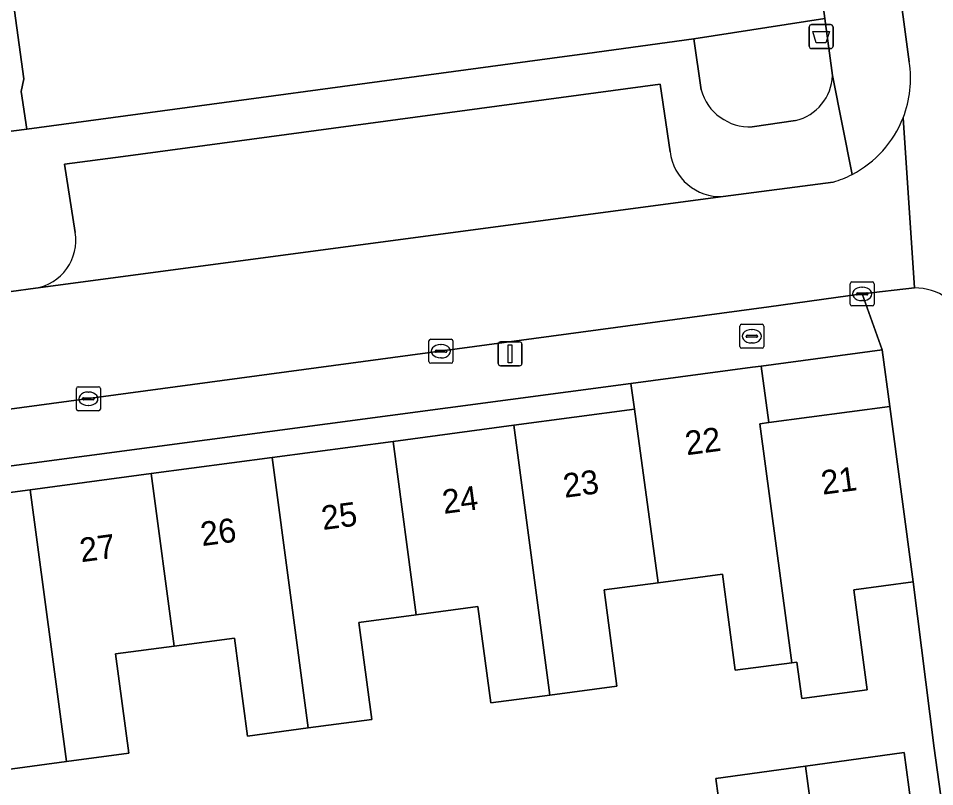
# Model space of a CAD drawing. Extents: x 163147 to 163550, y 380933 to 381639.
# Drawn here: x 163393.71 to 163431.91, y 381151.62 to 381183.65 of the extents above; entities that cross this region are included whole.
import ezdxf

# ---------------------------------------------------------------- set-up
doc = ezdxf.new("R2010")
doc.units = 0
for name, color, linetype in [('IMGEO_Afvalbak', 7, 'Continuous'), ('IMGEO_Brandkraan', 7, 'Continuous'), ('IMGEO_Erf', 7, 'Continuous'), ('IMGEO_Groenvoorziening', 7, 'Continuous'), ('IMGEO_Kolk', 7, 'Continuous'), ('IMGEO_Lichtmast', 7, 'Continuous'), ('IMGEO_Muur', 7, 'Continuous'), ('IMGEO_Pand', 7, 'Continuous'), ('IMGEO_Pand_nummerreeks', 7, 'Continuous'), ('IMGEO_Parkeervlak_open', 7, 'Continuous'), ('IMGEO_Rijbaan_lokaal_open', 7, 'Continuous'), ('IMGEO_Voetpad_gesloten', 7, 'Continuous'), ('IMGEO_Voetpad_open', 7, 'Continuous')]:
    doc.layers.add(name, color=color, linetype=linetype)

msp = doc.modelspace()

# ---------------------------------------------------------------- linework, layer by layer
at = {"layer": 'IMGEO_Afvalbak'}
for p, q in [((163426.682, 381182.493), (163426.682, 381183.293)), ((163426.682, 381183.293), (163426.682, 381182.493)), ((163426.782, 381183.393), (163427.572, 381183.393)), ((163427.572, 381183.393), (163426.782, 381183.393)), ((163427.672, 381183.293), (163427.672, 381182.493)), ((163427.672, 381182.493), (163427.672, 381183.293)), ((163427.572, 381182.393), (163426.782, 381182.393)), ((163426.782, 381182.393), (163427.572, 381182.393))]:
    msp.add_line(p, q, dxfattribs=at)
msp.add_lwpolyline([(163426.825, 381183.107), (163427.529, 381183.107), (163427.38, 381182.637), (163426.974, 381182.637), (163426.825, 381183.107)], dxfattribs=at)
for centre, start, end in [((163426.782, 381183.293), 90, 180), ((163426.782, 381183.293), 90, 180), ((163427.572, 381183.293), 0, 90), ((163427.572, 381183.293), 360, 90), ((163426.782, 381182.493), 180, 270), ((163426.782, 381182.493), 180, 270), ((163427.572, 381182.493), 270, 0), ((163427.572, 381182.493), 270, 0)]:
    msp.add_arc(centre, 0.1, start, end, dxfattribs=at)
at = {"layer": 'IMGEO_Brandkraan'}
for p, q in [((163423.863, 381170.899), (163424.715, 381170.899)), ((163423.788, 381169.973), (163423.788, 381170.825)), ((163424.276, 381170.679), (163424.301, 381170.679)), ((163424.789, 381170.825), (163424.789, 381169.973)), ((163424.047, 381170.393), (163424.047, 381170.405)), ((163424.485, 381170.356), (163424.087, 381170.356)), ((163424.09, 381170.442), (163424.488, 381170.442)), ((163424.299, 381170.119), (163424.274, 381170.119)), ((163424.531, 381170.405), (163424.531, 381170.393)), ((163424.715, 381169.899), (163423.863, 381169.899))]:
    msp.add_line(p, q, dxfattribs=at)
for points in [[(163423.863, 381170.899), (163424.715, 381170.899)], [(163423.788, 381169.973), (163423.788, 381170.825)], [(163424.789, 381170.825), (163424.789, 381169.973)], [(163424.715, 381169.899), (163423.863, 381169.899)]]:
    msp.add_lwpolyline(points, dxfattribs=at)
for centre, radius, start, end in [((163423.865, 381170.823), 0.0765, 91.552, 178.448), ((163423.865, 381170.823), 0.0765, 91.552, 178.448), ((163424.713, 381170.823), 0.0765, 1.552, 88.448), ((163424.713, 381170.823), 0.0765, 1.552, 88.448), ((163424.087, 381170.402), 0.0403, 85.8775, 175.7526), ((163424.084, 381170.392), 0.0366, 178.938, 274.7102), ((163424.488, 381170.399), 0.043, 264.8664, 352.4533), ((163424.492, 381170.404), 0.0386, 1.7309, 96.639), ((163423.865, 381169.975), 0.0765, 181.552, 268.448), ((163423.865, 381169.975), 0.0765, 181.552, 268.448), ((163424.713, 381169.975), 0.0765, 271.552, 358.448), ((163424.713, 381169.975), 0.0765, 271.552, 358.448)]:
    msp.add_arc(centre, radius, start, end, dxfattribs=at)
for centre, major_axis, ratio, start_param, end_param in [((163424.275, 381170.399), (-0.387, 0.002), 0.722429, 4.712389, 7.853982), ((163424.3, 381170.399), (-0.39, 0.002), 0.717154, 1.570796, 4.712389)]:
    msp.add_ellipse(centre, major_axis=major_axis, ratio=ratio, start_param=start_param, end_param=end_param, dxfattribs=at)
at = {"layer": 'IMGEO_Erf'}
for points in [[(163424.677, 381169.157), (163424.991, 381166.799), (163430.04, 381167.473), (163429.716, 381169.834)], [(163368.864, 381161.727), (163369.01, 381160.644), (163374.049, 381161.316), (163379.091, 381161.987), (163384.131, 381162.659), (163389.171, 381163.33), (163394.211, 381164.002), (163399.252, 381164.673), (163404.292, 381165.345), (163409.333, 381166.017), (163414.374, 381166.688), (163419.394, 381167.357), (163419.25, 381168.435)]]:
    msp.add_lwpolyline(points, close=True, dxfattribs=at)
for points in [[(163432.293, 381150.328), (163431.895, 381153.22), (163431.015, 381160.154), (163428.536, 381159.824), (163429.09, 381155.665), (163426.367, 381155.302), (163426.165, 381156.816), (163425.955, 381156.788), (163423.599, 381156.475), (163423.065, 381160.483), (163420.38, 381160.125), (163418.128, 381159.825), (163418.662, 381155.814), (163415.874, 381155.442), (163413.405, 381155.113), (163412.871, 381159.126), (163410.298, 381158.783), (163407.907, 381158.464), (163408.445, 381154.424), (163405.797, 381154.071), (163403.262, 381153.733), (163402.718, 381157.814), (163400.212, 381157.48), (163397.769, 381157.155), (163398.32, 381153.012), (163395.724, 381152.666), (163393.158, 381152.324)], [(163423.179, 381149.073), (163422.784, 381151.966), (163426.53, 381152.481), (163430.634, 381153.046), (163431.032, 381150.154)]]:
    msp.add_lwpolyline(points, dxfattribs=at)
at = {"layer": 'IMGEO_Groenvoorziening'}
for points in [[(163392.619, 381190.656), (163393.942, 381181.127), (163393.833, 381180.6), (163394.068, 381179.029), (163416.481, 381182.062), (163417.426, 381182.19), (163421.871, 381182.792), (163427.334, 381183.638), (163426.58, 381189.302), (163426.448, 381190.297)], [(163427.649, 381181.274), (163427.334, 381183.638), (163421.871, 381182.792), (163422.171, 381180.674)], [(163424.308, 381179.127), (163426.103, 381179.391)]]:
    msp.add_lwpolyline(points, dxfattribs=at)
for centre, radius, start, end in [((163425.656, 381181.334), 1.994, 282.9625, 358.2634), ((163424.207, 381181.237), 2.112, 195.4506, 272.7469)]:
    msp.add_arc(centre, radius, start, end, dxfattribs=at)
at = {"layer": 'IMGEO_Kolk'}
for p, q in [((163428.386, 381171.736), (163428.386, 381172.588)), ((163428.461, 381172.662), (163429.313, 381172.662)), ((163428.874, 381172.442), (163428.899, 381172.442)), ((163429.387, 381172.588), (163429.387, 381171.736)), ((163428.645, 381172.156), (163428.645, 381172.168)), ((163429.083, 381172.119), (163428.685, 381172.119)), ((163428.688, 381172.205), (163429.086, 381172.205)), ((163429.129, 381172.168), (163429.129, 381172.156)), ((163429.313, 381171.662), (163428.461, 381171.662)), ((163428.897, 381171.882), (163428.872, 381171.882)), ((163410.828, 381169.349), (163410.828, 381170.201)), ((163410.903, 381170.275), (163411.755, 381170.275)), ((163411.829, 381170.201), (163411.829, 381169.349)), ((163411.087, 381169.769), (163411.087, 381169.781)), ((163411.525, 381169.732), (163411.127, 381169.732)), ((163411.13, 381169.818), (163411.528, 381169.818)), ((163411.316, 381170.055), (163411.341, 381170.055)), ((163411.571, 381169.781), (163411.571, 381169.769)), ((163411.339, 381169.495), (163411.314, 381169.495)), ((163411.755, 381169.275), (163410.903, 381169.275)), ((163396.131, 381167.365), (163396.131, 381168.217)), ((163396.206, 381168.291), (163397.058, 381168.291)), ((163397.132, 381168.217), (163397.132, 381167.365)), ((163396.39, 381167.785), (163396.39, 381167.797)), ((163396.433, 381167.834), (163396.831, 381167.834)), ((163396.619, 381168.071), (163396.644, 381168.071)), ((163396.874, 381167.797), (163396.874, 381167.785)), ((163396.828, 381167.748), (163396.43, 381167.748)), ((163396.642, 381167.511), (163396.617, 381167.511)), ((163397.058, 381167.291), (163396.206, 381167.291))]:
    msp.add_line(p, q, dxfattribs=at)
for points in [[(163428.386, 381171.736), (163428.386, 381172.588)], [(163428.461, 381172.662), (163429.313, 381172.662)], [(163429.387, 381172.588), (163429.387, 381171.736)], [(163429.313, 381171.662), (163428.461, 381171.662)], [(163410.828, 381169.349), (163410.828, 381170.201)], [(163410.903, 381170.275), (163411.755, 381170.275)], [(163411.829, 381170.201), (163411.829, 381169.349)], [(163411.755, 381169.275), (163410.903, 381169.275)], [(163396.131, 381167.365), (163396.131, 381168.217)], [(163396.206, 381168.291), (163397.058, 381168.291)], [(163397.132, 381168.217), (163397.132, 381167.365)], [(163397.058, 381167.291), (163396.206, 381167.291)]]:
    msp.add_lwpolyline(points, dxfattribs=at)
for centre, radius, start, end in [((163428.463, 381172.586), 0.0765, 91.552, 178.448), ((163428.463, 381172.586), 0.0765, 91.552, 178.448), ((163429.311, 381172.586), 0.0765, 1.552, 88.448), ((163429.311, 381172.586), 0.0765, 1.552, 88.448), ((163428.685, 381172.165), 0.0403, 85.8775, 175.7526), ((163428.682, 381172.155), 0.0366, 178.938, 274.7102), ((163429.086, 381172.162), 0.043, 264.8664, 352.4533), ((163429.09, 381172.167), 0.0386, 1.7309, 96.639), ((163428.463, 381171.738), 0.0765, 181.552, 268.448), ((163428.463, 381171.738), 0.0765, 181.552, 268.448), ((163429.311, 381171.738), 0.0765, 271.552, 358.448), ((163429.311, 381171.738), 0.0765, 271.552, 358.448), ((163410.905, 381170.199), 0.0765, 91.552, 178.448), ((163410.905, 381170.199), 0.0765, 91.552, 178.448), ((163411.753, 381170.199), 0.0765, 1.552, 88.448), ((163411.753, 381170.199), 0.0765, 1.552, 88.448), ((163411.127, 381169.778), 0.0403, 85.8775, 175.7526), ((163411.124, 381169.768), 0.0366, 178.938, 274.7102), ((163411.528, 381169.775), 0.043, 264.8664, 352.4533), ((163411.532, 381169.78), 0.0386, 1.7309, 96.639), ((163410.905, 381169.351), 0.0765, 181.552, 268.448), ((163410.905, 381169.351), 0.0765, 181.552, 268.448), ((163411.753, 381169.351), 0.0765, 271.552, 358.448), ((163411.753, 381169.351), 0.0765, 271.552, 358.448), ((163396.208, 381168.215), 0.0765, 91.552, 178.448), ((163396.208, 381168.215), 0.0765, 91.552, 178.448), ((163397.056, 381168.215), 0.0765, 1.552, 88.448), ((163397.056, 381168.215), 0.0765, 1.552, 88.448), ((163396.43, 381167.794), 0.0403, 85.8775, 175.7526), ((163396.835, 381167.796), 0.0386, 1.7309, 96.639), ((163396.427, 381167.784), 0.0366, 178.938, 274.7102), ((163396.831, 381167.791), 0.043, 264.8664, 352.4533), ((163396.208, 381167.367), 0.0765, 181.552, 268.448), ((163396.208, 381167.367), 0.0765, 181.552, 268.448), ((163397.056, 381167.367), 0.0765, 271.552, 358.448), ((163397.056, 381167.367), 0.0765, 271.552, 358.448)]:
    msp.add_arc(centre, radius, start, end, dxfattribs=at)
for centre, major_axis, ratio, start_param, end_param in [((163428.873, 381172.162), (-0.387, 0.002), 0.722429, 4.712389, 7.853982), ((163428.898, 381172.162), (-0.39, 0.002), 0.717154, 1.570796, 4.712389), ((163411.315, 381169.775), (-0.387, 0.002), 0.722429, 4.712389, 7.853982), ((163411.34, 381169.775), (-0.39, 0.002), 0.717154, 1.570796, 4.712389), ((163396.618, 381167.791), (-0.387, 0.002), 0.722429, 4.712389, 7.853982), ((163396.643, 381167.791), (-0.39, 0.002), 0.717154, 1.570796, 4.712389)]:
    msp.add_ellipse(centre, major_axis=major_axis, ratio=ratio, start_param=start_param, end_param=end_param, dxfattribs=at)
at = {"layer": 'IMGEO_Lichtmast'}
for p, q in [((163413.815, 381170.165), (163414.605, 381170.165)), ((163414.605, 381170.165), (163413.815, 381170.165)), ((163413.715, 381169.265), (163413.715, 381170.065)), ((163413.715, 381170.065), (163413.715, 381169.265)), ((163414.705, 381170.065), (163414.705, 381169.265)), ((163414.705, 381169.265), (163414.705, 381170.065)), ((163414.605, 381169.165), (163413.815, 381169.165)), ((163413.815, 381169.165), (163414.605, 381169.165))]:
    msp.add_line(p, q, dxfattribs=at)
msp.add_lwpolyline([(163414.135, 381170.04), (163414.285, 381170.04), (163414.285, 381169.29), (163414.135, 381169.29), (163414.135, 381170.04)], dxfattribs=at)
for centre, start, end in [((163413.815, 381170.065), 90, 180), ((163413.815, 381170.065), 90, 180), ((163414.605, 381170.065), 0, 90), ((163414.605, 381170.065), 360, 90), ((163413.815, 381169.265), 180, 270), ((163413.815, 381169.265), 180, 270), ((163414.605, 381169.265), 270, 0), ((163414.605, 381169.265), 270, 0)]:
    msp.add_arc(centre, 0.1, start, end, dxfattribs=at)
at = {"layer": 'IMGEO_Muur'}
msp.add_lwpolyline([(163431.895, 381153.22), (163431.015, 381160.154)], dxfattribs=at)
at = {"layer": 'IMGEO_Pand'}
for points in [[(163424.625, 381166.75), (163424.991, 381166.799), (163424.677, 381169.157), (163424.31, 381169.108), (163419.25, 381168.435), (163419.394, 381167.357), (163420.38, 381160.125), (163423.065, 381160.483), (163423.599, 381156.475), (163425.955, 381156.788)], [(163430.04, 381167.473), (163424.991, 381166.799), (163424.625, 381166.75), (163425.955, 381156.788), (163426.165, 381156.816), (163426.367, 381155.302), (163429.09, 381155.665), (163428.536, 381159.824), (163431.015, 381160.154)], [(163414.374, 381166.688), (163415.874, 381155.442), (163418.662, 381155.814), (163418.128, 381159.825), (163420.38, 381160.125), (163419.394, 381167.357)], [(163414.374, 381166.688), (163409.333, 381166.017), (163410.298, 381158.783), (163412.871, 381159.126), (163413.405, 381155.113), (163415.874, 381155.442)], [(163410.298, 381158.783), (163409.333, 381166.017), (163404.292, 381165.345), (163405.797, 381154.071), (163408.445, 381154.424), (163407.907, 381158.464)], [(163399.252, 381164.673), (163400.212, 381157.48), (163402.718, 381157.814), (163403.262, 381153.733), (163405.797, 381154.071), (163404.292, 381165.345)], [(163394.211, 381164.002), (163395.724, 381152.666), (163398.32, 381153.012), (163397.769, 381157.155), (163400.212, 381157.48), (163399.252, 381164.673)], [(163394.211, 381164.002), (163389.171, 381163.33), (163390.128, 381156.164), (163392.603, 381156.493), (163393.158, 381152.324), (163395.724, 381152.666)], [(163426.53, 381152.481), (163426.916, 381149.587), (163431.032, 381150.154), (163430.634, 381153.046)], [(163426.53, 381152.481), (163422.784, 381151.966), (163423.179, 381149.073), (163426.916, 381149.587)]]:
    msp.add_lwpolyline(points, close=True, dxfattribs=at)
at = {"layer": 'IMGEO_Parkeervlak_open'}
for points in [[(163420.881, 381178.091), (163420.467, 381180.905), (163398.088, 381177.893), (163395.641, 381177.574), (163396.079, 381174.725)], [(163394.422, 381172.398), (163423.091, 381176.226)]]:
    msp.add_lwpolyline(points, dxfattribs=at)
for centre, radius, start, end in [((163422.979, 381178.336), 2.113, 186.6483, 273.0303), ((163394.095, 381174.384), 2.013, 279.3509, 9.7417)]:
    msp.add_arc(centre, radius, start, end, dxfattribs=at)
at = {"layer": 'IMGEO_Rijbaan_lokaal_open'}
for points in [[(163435.88, 381180.272), (163435.633, 381182.277), (163435.404, 381184.201), (163434.853, 381188.435), (163432.818, 381203.407), (163430.773, 381218.81), (163425.989, 381218.194), (163426.029, 381217.897), (163430.333, 381185.704), (163430.851, 381181.833)], [(163424.996, 381171.625), (163428.886, 381172.164), (163431.075, 381172.412), (163430.598, 381179.51)], [(163430.598, 381179.51), (163431.075, 381172.412)], [(163427.684, 381176.827), (163423.091, 381176.226), (163394.422, 381172.398), (163393.415, 381172.264), (163364.797, 381168.442), (163364.62, 381168.418), (163360.766, 381167.906)], [(163360.74, 381162.963), (163424.996, 381171.625)]]:
    msp.add_lwpolyline(points, dxfattribs=at)
for centre, radius, start, end in [((163426.406, 381181.142), 4.498, 338.7298, 8.8389), ((163426.402, 381181.144), 4.503, 297.2797, 338.7245), ((163426.431, 381181.065), 4.419, 286.4669, 297.4136), ((163431.094, 381170.142), 2.27, 54.4921, 90.4732)]:
    msp.add_arc(centre, radius, start, end, dxfattribs=at)
at = {"layer": 'IMGEO_Voetpad_gesloten'}
msp.add_lwpolyline([(163390.483, 381190.847), (163391.936, 381180.845), (163392.125, 381180.355), (163392.322, 381178.807), (163394.068, 381179.029), (163393.833, 381180.6), (163393.942, 381181.127), (163392.619, 381190.656)], dxfattribs=at)
at = {"layer": 'IMGEO_Voetpad_open'}
for points in [[(163411.738, 381300.577), (163412.04, 381298.473), (163412.615, 381298.564), (163412.943, 381296.173), (163412.333, 381296.085), (163413.391, 381288.172), (163413.621, 381286.452), (163413.923, 381284.196), (163414.377, 381280.796), (163414.835, 381277.372), (163416.363, 381265.945), (163418.495, 381250), (163420.601, 381234.252), (163422.371, 381221.02), (163422.878, 381217.111), (163426.448, 381190.297), (163426.58, 381189.302), (163427.334, 381183.638), (163427.649, 381181.274), (163428.466, 381177.142)], [(163430.851, 381181.833), (163430.333, 381185.704)], [(163422.171, 381180.674), (163421.871, 381182.792), (163417.426, 381182.19), (163416.481, 381182.062), (163394.068, 381179.029), (163392.322, 381178.807), (163364.157, 381175.08), (163364.415, 381172.977)], [(163428.466, 381177.142), (163427.649, 381181.274)], [(163396.079, 381174.725), (163395.641, 381177.574), (163398.088, 381177.893), (163420.467, 381180.905)], [(163420.467, 381180.905), (163420.881, 381178.091)], [(163426.103, 381179.391), (163424.308, 381179.127)], [(163423.091, 381176.226), (163427.684, 381176.827)], [(163393.415, 381172.264), (163394.422, 381172.398)], [(163431.075, 381172.412), (163428.886, 381172.164), (163429.716, 381169.834), (163430.04, 381167.473), (163431.015, 381160.154), (163431.895, 381153.22), (163432.293, 381150.328), (163432.505, 381148.832), (163433.187, 381144.015), (163433.211, 381143.836), (163433.885, 381138.765), (163433.927, 381138.448), (163437.919, 381108.562), (163437.948, 381108.344), (163438.622, 381103.273), (163438.642, 381103.121), (163439.201, 381098.033), (163440.974, 381089.977)]]:
    msp.add_lwpolyline(points, dxfattribs=at)
msp.add_lwpolyline([(163428.886, 381172.164), (163424.996, 381171.625), (163360.74, 381162.963), (163359.144, 381160.427), (163363.561, 381161.021), (163363.824, 381161.056), (163368.864, 381161.727), (163419.25, 381168.435), (163424.31, 381169.108), (163424.677, 381169.157), (163429.716, 381169.834)], close=True, dxfattribs=at)
for centre, radius, start, end in [((163426.406, 381181.142), 4.498, 338.7298, 8.8389), ((163425.656, 381181.334), 1.994, 282.9625, 358.2634), ((163424.207, 381181.237), 2.112, 195.4506, 272.7469), ((163426.402, 381181.144), 4.503, 297.2797, 338.7245), ((163422.979, 381178.336), 2.113, 186.6483, 273.0303), ((163426.431, 381181.065), 4.419, 286.4669, 297.4136), ((163394.095, 381174.384), 2.013, 279.3509, 9.7417), ((163431.094, 381170.142), 2.27, 54.4921, 90.4732)]:
    msp.add_arc(centre, radius, start, end, dxfattribs=at)

# ---------------------------------------------------------------- texts
at = {"layer": 'IMGEO_Pand_nummerreeks'}
for s, rotation, p in [('22', 7.5802, (163421.574, 381165.434)), ('23', 7.5891, (163416.489, 381163.661)), ('21', 7.6031, (163427.242, 381163.79)), ('24', 7.5891, (163411.45, 381162.989)), ('25', 7.5891, (163406.412, 381162.318)), ('26', 7.5891, (163401.373, 381161.647)), ('27', 7.5891, (163396.335, 381160.976))]:
    msp.add_text(s, height=1, rotation=rotation, dxfattribs=at).set_placement(p)

doc.saveas('drawing.dxf')
